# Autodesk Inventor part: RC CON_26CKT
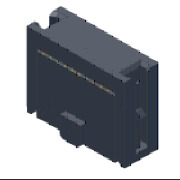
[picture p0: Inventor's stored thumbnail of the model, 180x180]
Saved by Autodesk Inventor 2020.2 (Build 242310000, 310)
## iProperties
Manager: www.cadconsulting.pl
Company: Fabian Stasiak CAD Consulting
Created: 2014-02
Part Number: RC CON_26CKT
Material: Ogólny
Description: Podziałka 2.54mm (0.10cala), gniazdo, pionowe, dwurzędowe
Document SubType Name: Modeling
Designer: F.Stasiak
Language: pl-PL
Size Designation: Ribbon Cable Connector-06
Categories: <MemberInstance><Categories><Category DisplayName="Kable i wiązki przewodów" InternalName="e4a7e005-5e42-4d16-b293-125e7f0d0512" Mnemonic="CABLEANDHARNESS"><Cat
Density: 1 g/cm^3
Appearance: Dark Gray
Catalog Web Link: www.expertbooks.pl
IsCustomPart: 0
Author: F.Stasiak
Subject: Zbiór ćwiczeń. Autodesk Inventor 2020. Kurs Professional
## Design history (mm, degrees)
sketch "Sketch1"
  geometry: L1 (17.14, -3)-(-17.14, -3); L2 (-16.39, -1.5)-(-16.39, -2.1); L3 (-17.14, -3)-(-17.14, -2.1); L4 (-16.39, -2.1)-(-17.14, -2.1); L5 (-17.14, -1.5)-(-16.39, -1.5); L6 (-17.14, -1.5)-(-17.14, 3); L7 (16.39, 1.5)-(16.39, 2.1); L8 (17.14, 1.5)-(17.14, -3); L9 (17.14, 1.5)-(16.39, 1.5); L10 (16.39, 2.1)-(17.14, 2.1); L11 (17.14, 3)-(17.14, 2.1); L12 (0, 3)-(0, -3); L13 (-17.14, 3)-(17.14, 3); 2 further points
  constraints: 26 end point, 8 parallel, 3 midpoint, 3 perpendicular, 2 horizontal, 1 coincident
  dimensions: "d0" = 34.28 distance of L1.start L1.end (derived); "d1" = 6 distance of L1.end L6.end; "d4" = 0.9 distance between parallel lines of L1 L4; "d5" = 0.75 distance of L2.end L3.end; "d6" = 0.6 distance of L2.start L2.end; "d8" = 0.75 distance of L7.end L10.end; "d9" = 0.6 distance of L7.start L7.end; "d10" = 6 distance of L1.start L11.start; "d12" = 0.9 distance of L11.start L10.end
extrude "Wyciągnięcie1" new body sketch "Sketch1" distance "d13" = 10.2; taper "d14" = 0 deg
sketch "Sketch2"
  geometry: L1 (0, 0)-(34.28, 0) reference; L2 (15.34, 3.6)-(18.94, 3.6); L3 (18.94, 3.6)-(18.94, 0.5); L4 (18.44, 0)-(15.84, 0); L5 (15.34, 0.5)-(15.34, 3.6); L6 (15.34, 0.5)-(15.84, 0); L7 (18.94, 0.5)-(18.44, 0); 1 further point
  constraints: 12 end point, 2 midpoint, 2 parallel, 1 horizontal, 1 perpendicular
  dimensions: "d15" = 3.6 distance of L2.start L2.end; "d17" = 0.5 horizontal distance of L4.end L5.start; "d19" = 135 deg angle of L6 L5; "d20" = 135 deg angle of L7 L3; "d21" = 0.5 horizontal distance of L4.start L3.end; "d22" = 3.6 distance between parallel lines of L1 L2
extrude "Wyciągnięcie2" join sketch "Sketch2" distance "d23" = 1; taper "d24" = 0 deg
sketch "Sketch3"
  geometry: L1 (-17.14, 3.6)-(-17.39, 3.6); L2 (-18.14, 2.1)-(-18.14, 1.22); L3 (-18.14, 1.22)-(-17.14, 1.22); L4 (-17.14, 1.22)-(-17.14, 3.6); L5 (17.14, 10.2)-(-17.14, 10.2) reference; L6 (0, 10.2)-(0, 0); L7 (-17.14, 0)-(17.14, 0) reference; L8 (-17.39, 3.6)-(-18.14, 2.1); L9 (17.14, 3.6)-(17.39, 3.6); L10 (18.14, 2.1)-(18.14, 1.22); L11 (18.14, 1.22)-(17.14, 1.22); L12 (17.14, 1.22)-(17.14, 3.6); L13 (17.39, 3.6)-(18.14, 2.1)
  constraints: 22 end point, 5 symmetric about line, 2 midpoint, 2 parallel, 2 perpendicular, 1 horizontal
  dimensions: "d25" = 34.28 diameter of L4 L6 (derived); "d26" = 1.22 distance between parallel lines of L3 L7; "d28" = 1 distance of L2.end L3.end; "d29" = 1.5 vertical distance of L1.end L2.start; "d30" = 0.88 distance of L2.start L2.end; "d31" = 0.25 distance of L1.start L1.end
extrude "Wyciągnięcie3" join sketch "Sketch3" stored distance "d32" = 1; taper "d33" = 0 deg
sketch "Sketch4"
  geometry: L1 (17.14, 3.6)-(17.39, 3.6) reference; L2 (17.14, 6.263)-(17.39, 6.263); L3 (18.14, 5.513)-(18.14, 5.263); L4 (18.14, 5.263)-(17.14, 5.263); L5 (17.14, 5.263)-(17.14, 6.263); L6 (-17.14, 10.2)-(17.14, 10.2) reference; L7 (17.14, 0)-(-17.14, 0) reference; L8 (0, 10.2)-(0, 0); L9 (17.39, 6.263)-(18.14, 5.513); L10 (-17.14, 5.263)-(-17.14, 6.263); L11 (-17.14, 6.263)-(-17.39, 6.263); L12 (-17.39, 6.263)-(-18.14, 5.513); L13 (-18.14, 5.513)-(-18.14, 5.263); L14 (-18.14, 5.263)-(-17.14, 5.263)
  constraints: 22 end point, 5 symmetric about line, 2 midpoint, 2 parallel, 1 horizontal, 1 perpendicular
  dimensions: "d34" = 1.663 distance between parallel lines of L4 L1; "d35" = 34.28 diameter of L5 L8 (derived); "d36" = 1 distance of L3.end L4.end; "d38" = 0.25 distance of L2.start L2.end; "d39" = 1 distance of L4.end L2.start; "d40" = 0.25 distance of L3.start L3.end
extrude "Wyciągnięcie4" join sketch "Sketch4" distance "d41" = 1; taper "d42" = 0 deg
sketch "Sketch5"
  geometry: L1 (17.39, -3.6)-(17.14, -3.6) reference; L2 (17.39, -6.263)-(17.14, -6.263); L3 (17.14, -6.263)-(17.14, -5.263); L4 (17.14, -5.263)-(18.14, -5.263); L5 (18.14, -5.263)-(18.14, -5.513); L6 (17.14, -10.2)-(-17.14, -10.2) reference; L7 (1.3, 0)-(-1.3, 0) reference; L8 (0, 0)-(0, -10.2); L9 (17.39, -6.263)-(18.14, -5.513); L10 (-17.14, -6.263)-(-17.14, -5.263); L11 (-17.39, -6.263)-(-17.14, -6.263); L12 (-17.39, -6.263)-(-18.14, -5.513); L13 (-18.14, -5.263)-(-18.14, -5.513); L14 (-17.14, -5.263)-(-18.14, -5.263)
  constraints: 22 end point, 5 symmetric about line, 2 midpoint, 2 parallel, 1 horizontal, 1 perpendicular
  dimensions: "d43" = 1.663 distance between parallel lines of L1 L4; "d44" = 34.28 diameter of L3 L8 (derived); "d45" = 1 distance of L2.end L3.end; "d46" = 1 distance of L3.end L4.end; "d47" = 0.25 distance of L2.start L2.end; "d48" = 0.25 distance of L4.end L5.end
extrude "Wyciągnięcie5" join sketch "Sketch5" distance "d49" = 1; taper "d50" = 0 deg
sketch "Sketch6"
  geometry: L1 (0, -10.2)-(15.84, -10.2) reference; L2 (-36.97, -6.736)-(-34.97, -10.2); L3 (-38.97, -10.2)-(-36.97, -6.736); L4 (-38.97, -10.2)-(-34.97, -10.2); L5 (0.5, -10.2)-(2.5, -6.736); L6 (2.5, -6.736)-(4.5, -10.2); L7 (0.5, -10.2)-(4.5, -10.2)
  constraints: 12 end point, 4 equal length, 2 point on line, 1 collinear
  dimensions: "d61" = 0.5 distance of L5.start L1.start; "d62" = 4 distance of L5.start L6.end
extrude "Wyciągnięcie6" cut sketch "Sketch6" distance "d63" = 0.1; taper "d64" = 0 deg
sketch "Sketch7"
  geometry: L1 (17.14, 3)-(17.14, -1.5) reference; L2 (14.865, 1.645)-(15.615, 1.645); L3 (15.615, 1.645)-(15.615, 0.895); L4 (15.615, 0.895)-(14.865, 0.895); L5 (14.865, 0.895)-(14.865, 1.645); L6 (14.865, -0.895)-(15.615, -0.895); L7 (15.615, -0.895)-(15.615, -1.645); L8 (15.615, -1.645)-(14.865, -1.645); L9 (14.865, -1.645)-(14.865, -0.895); L10 (15.24, 0.895)-(15.24, -0.895); 2 further points
  constraints: 18 end point, 7 equal length, 4 parallel, 3 midpoint, 3 perpendicular, 2 horizontal, 1 horizontal alignment
  dimensions: "d65" = 0.75 distance of L2.start L2.end; "d66" = 2.54 distance between parallel lines of L6 L2; "d67" = 1.525 distance between parallel lines of L1 L7
extrude "Wyciągnięcie7" cut sketch "Sketch7" distance "d68" = 3; taper "d69" = 0 deg
pattern_linear "Wzór prostokątny1" dims "d75" = 2.54
workplane "Work Plane1"
sketch "Sketch8"
  geometry: L1 (-18.121, -1.499)-(-17.27, -1.499); L2 (-18.825, -1.03)-(-18.121, -1.499); L3 (-18.825, -3.03)-(-18.825, -1.03); L4 (18.825, -3.03)-(-18.825, -3.03); L5 (-18.825, 3.03)-(18.825, 3.03); L6 (-17.27, -1.499)-(-17.27, 1.499); L7 (-17.14, 3)-(17.14, 3) reference; L8 (-17.14, -1.5)-(-17.14, 3) reference; L9 (-16.39, -1.5)-(-17.14, -1.5) reference; L10 (-16.39, -2.1)-(-16.39, -1.5) reference; L11 (-17.14, -2.1)-(-16.39, -2.1) reference; L12 (-17.14, -3)-(-17.14, -2.1) reference; L13 (17.14, -3)-(-17.14, -3) reference; L14 (17.14, 1.5)-(17.14, -3) reference; L15 (16.39, 1.5)-(17.14, 1.5) reference; L16 (16.39, 2.1)-(16.39, 1.5) reference; L17 (17.14, 2.1)-(16.39, 2.1) reference; L18 (17.14, 3)-(17.14, 2.1) reference; L19 (0, 3)-(0, -3); L20 (-17.27, 0)-(-42.954, 0); L21 (-18.825, 1.03)-(-18.121, 1.499); L22 (-18.825, 3.03)-(-18.825, 1.03); L23 (-18.121, 1.499)-(-17.27, 1.499); L24 (18.825, 3.03)-(18.825, 1.03); L25 (18.825, 1.03)-(18.121, 1.499); L26 (18.121, 1.499)-(17.27, 1.499); L27 (17.27, -1.499)-(17.27, 1.499); L28 (18.121, -1.499)-(17.27, -1.499); L29 (18.825, -1.03)-(18.121, -1.499); L30 (18.825, -3.03)-(18.825, -1.03); 4 further points
  constraints: 36 end point, 8 symmetric about line, 5 midpoint, 4 perpendicular, 3 parallel, 1 coincident, 1 horizontal, 1 horizontal alignment
  dimensions: "d160" = 2 distance of L3.start L2.start; "d161" = 0.85079 distance of L1.start L1.end; "d162" = 2.99894 distance of L1.end L6.end; "d163" = 56.3099 deg angle of L3 L2; "d164" = 0.13 distance between parallel lines of L8 L6; "d165" = 37.65 distance of L5.start L5.end (derived)
extrude "Wyciągnięcie8" join sketch "Sketch8" distance "d90" = 2.5; taper "d91" = 0 deg
sketch "Sketch10"
  geometry: L1 (-18.825, 3.03)-(-18.825, 1.03) reference; L2 (18.825, 3.03)-(-18.825, 3.03) reference; L3 (18.825, 1.03)-(18.825, 3.03) reference; L4 (18.121, 1.499)-(18.825, 1.03) reference; L5 (17.27, 1.499)-(18.121, 1.499) reference; L6 (17.27, -1.499)-(17.27, 1.499) reference; L7 (18.121, -1.499)-(17.27, -1.499) reference; L8 (18.825, -1.03)-(18.121, -1.499) reference; L9 (18.825, -3.03)-(18.825, -1.03) reference; L10 (-18.825, -3.03)-(18.825, -3.03) reference; L11 (-18.825, -1.03)-(-18.825, -3.03) reference; L12 (-18.121, -1.499)-(-18.825, -1.03) reference; L13 (-17.27, -1.499)-(-18.121, -1.499) reference; L14 (-17.27, 1.499)-(-17.27, -1.499) reference; L15 (-18.121, 1.499)-(-17.27, 1.499) reference; L16 (-18.825, 1.03)-(-18.121, 1.499) reference; L17 (17.14, -1.5)-(16.39, -1.5) reference; L18 (16.39, -1.5)-(16.39, -2.1) reference; L19 (16.39, -2.1)-(17.14, -2.1) reference; L20 (-17.14, 1.5)-(-16.39, 1.5) reference; L21 (-16.39, 1.5)-(-16.39, 2.1) reference; L22 (-16.39, 2.1)-(-17.14, 2.1) reference; L23 (-17.15, 1.51)-(-16.4, 1.51); L24 (-16.4, 1.51)-(-16.4, 2.09); L25 (-16.4, 2.09)-(-17.15, 2.09); L26 (-17.15, 2.09)-(-17.15, 3.03); L27 (17.15, -2.09)-(16.4, -2.09); L28 (16.4, -2.09)-(16.4, -1.51); L29 (16.4, -1.51)-(17.15, -1.51); L30 (17.15, -3.03)-(17.15, -2.09); L31 (-17.27, -1.499)-(-17.15, -1.499); L32 (-17.27, 1.499)-(-17.15, 1.499); L33 (-17.15, -3.03)-(-17.15, -1.499); L34 (-17.15, 1.499)-(-17.15, 1.51); L35 (17.27, 1.499)-(17.15, 1.499); L36 (17.27, -1.499)-(17.15, -1.499); L37 (17.15, -1.51)-(17.15, -1.499); L38 (17.15, 1.499)-(17.15, 3.03); 4 further points
  constraints: 32 end point, 8 perpendicular, 7 parallel, 4 midpoint, 4 point on line, 2 horizontal, 2 horizontal alignment
  dimensions: "d167" = 0.01 distance between parallel lines of L20 L23; "d168" = 0.01 distance between parallel lines of L21 L24; "d170" = 0.01 distance from line of L26 L22.end; "d172" = 0.01 distance between parallel lines of L19 L27; "d173" = 0.01 distance between parallel lines of L18 L28; "d174" = 0.01 distance from line of L30 L19.end; "d180" = 0.01 distance from line of L20.start L34; "d181" = 0.12 distance of L13.start L31.end; "d182" = 0.01 distance of L36.end L17.start; "d183" = 0.12 distance of L5.start L35.end
extrude "Wyciągnięcie9" join sketch "Sketch10" distance "d157" = 10.7; taper "d158" = 0 deg
sketch "Sketch12"
  geometry: L1 (18.825, 13.2)-(-18.825, 13.2) reference; L2 (0, 13.2)-(0, 4.865); L3 (-18.825, 13.2)-(-18.825, 0) reference; L4 (-18.825, 0)-(-17.15, 0); L5 (-17.15, 0)-(-17.15, 1.21); L6 (-17.15, 1.21)-(-18.825, 1.21); L7 (-18.825, 1.21)-(-18.825, 0); L8 (-17.39, 3.6)-(-17.14, 3.6) reference; L9 (-18.14, 2.1)-(-17.39, 3.6) reference; L10 (-18.14, 1.22)-(-18.14, 2.1) reference; L11 (-17.14, 1.22)-(-18.14, 1.22) reference; L12 (17.15, 0)-(17.15, 1.21); L13 (17.15, 1.21)-(18.825, 1.21); L14 (18.825, 1.21)-(18.825, 0); L15 (18.825, 0)-(17.15, 0); L16 (-17.14, 3.6)-(-17.14, 1.22) reference
  constraints: 18 end point, 4 symmetric about line, 2 parallel, 2 perpendicular, 1 horizontal, 1 midpoint
  dimensions: "d177" = 0.01 distance between parallel lines of L11 L6; "d243" = 1.675 distance of L3.end L4.end
extrude "Wyciągnięcie10" join sketch "Sketch12" stored distance "d178" = 6.06; taper "d179" = 0 deg
sketch "Sketch20" dims "d253" = 10
  geometry: L1 (37.65, -2.49)-(0, -2.49) reference; L2 (37.65, 0)-(37.65, -2.49) reference; L3 (37.65, 0)-(0, 0) reference; L4 (0, 0)-(0, -2.49) reference; L5 (35.965, -3)-(1.685, -3) reference; 68 further points
  constraints: 2 midpoint, 2 vertical alignment, 1 horizontal, 63 other
  dimensions: "d240" = 0.25 distance from line of L5 point (2.95, -2.75); "d241" = 0.25 distance from line of L5 point (18.825, -2.75); "d242" = 0.25 distance from line of L3 point (18.825, 0.25); "d247" = 15.875 distance of point (18.825, -2.75) point (2.95, -2.75) (derived); "d250" = 1.27 distance of point (2.95, -2.75) point (4.22, -2.75)
sketch "Sketch21"
  geometry: L1 (0, 2.49)-(37.65, 2.49) reference; L2 (0, 2.49)-(0, 0) reference; L3 (0, 0)-(37.65, 0) reference; L4 (37.65, 0)-(37.65, 2.49) reference; 2 further points
workpoint "Work Point1"
workpoint "Work Point2"
node "1"
node "2"
node "3"
node "4"
node "5"
node "6"
node "7"
node "8"
node "9"
node "10"
node "11"
node "12"
node "13"
node "14"
node "15"
node "16"
node "17"
node "18"
node "19"
node "20"
node "21"
node "22"
node "23"
node "24"
node "25"
node "26"
body "Solid1"
chamfer "Faza1" distance "d70" = 0.5; stored, may be unused: second distance "d71" = 2, angle "d72" = 45 deg
chamfer "Faza2" distance "d185" = 1; stored, may be unused: second distance "d186" = 2, angle "d187" = 45 deg
chamfer "Faza3" distance "d188" = 1.749; stored, may be unused: second distance "d189" = 2, angle "d190" = 45 deg
chamfer "Faza4" distance "d191" = 10.71; stored, may be unused: second distance "d192" = 0.03, angle "d193" = 45 deg
chamfer "Faza5" distance "d194" = 10.71; stored, may be unused: second distance "d195" = 0.03, angle "d196" = 45 deg
chamfer "Faza8" distance "d203" = 0.5; stored, may be unused: second distance "d204" = 0.03, angle "d205" = 45 deg
node "Projected Loop2"
node "Projected Loop3"
node "Projected Loop4"
other parameters: "DimA" = 34.28 [user parameter], "DimB" = 37.65 [user parameter], "DimC" = 15.875 [user parameter], "d123" = 0.01, "d126" = 0.01, "d148" = 0.01, "d152" = 0.01, "d166" = 0.01, "d169" = 0.01, "d171" = 0.01, "d175" = 0.01, "d234" = 10.7
